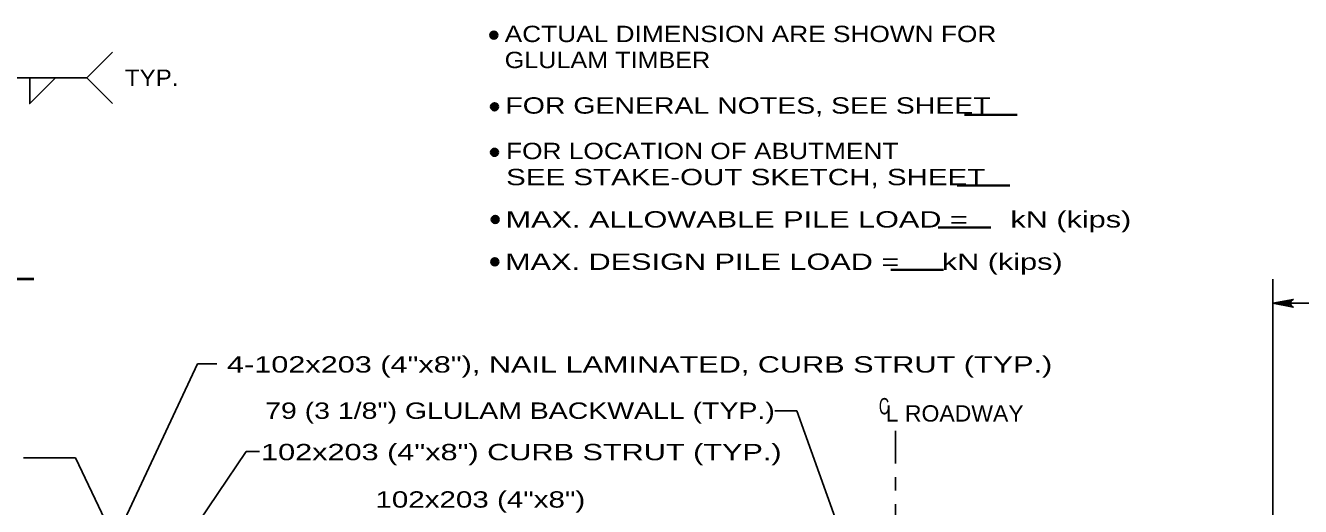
# Model space of a CAD drawing. Extents: x -6.4 to 73.1, y -66 to 0.
# Drawn here: x 41.66 to 51.01, y -58.56 to -55.03 of the extents above; entities that cross this region are included whole.
import ezdxf
from ezdxf.enums import TextEntityAlignment as Align

# ---------------------------------------------------------------- set-up
doc = ezdxf.new("R2010")
doc.units = 0
doc.header["$LTSCALE"] = 0.048
doc.linetypes.add('DOT_DASHED', pattern=[7.7, 5, -1.2, 0.3, -1.2])
for name, color, linetype, lineweight in [('3', 7, 'Continuous', 35), ('4', 7, 'Continuous', 25), ('5', 7, 'Continuous', 25)]:
    doc.layers.add(name, color=color, linetype=linetype, lineweight=lineweight)

msp = doc.modelspace()

# ---------------------------------------------------------------- hatches: boundary and pattern name
at = {"layer": '4'}
msp.add_hatch(color=256, dxfattribs=at).paths.add_polyline_path([(50.9215, -57.0485), (50.9215, -57.08783), (50.80342, -57.06817)])

# ---------------------------------------------------------------- linework, layer by layer
at = {"layer": '3', "lineweight": 25}
for p, q in [((42.10508, -55.41425), (42.29342, -55.22592)), ((40.91958, -55.41417), (42.10517, -55.41417)), ((42.10508, -55.41425), (42.29342, -55.60258))]:
    msp.add_line(p, q, dxfattribs=at)
msp.add_lwpolyline([(41.68692, -55.41417), (41.68692, -55.6025), (41.87525, -55.41417)], dxfattribs=at)
at = {"layer": '4', "lineweight": 35}
for p, q in [((48.54167, -55.68567), (48.92808, -55.68567)), ((48.48758, -56.20375), (48.874, -56.20375)), ((48.3485, -56.51308), (48.73492, -56.51308)), ((48.00067, -56.82242), (48.38708, -56.82242))]:
    msp.add_line(p, q, dxfattribs=at)
at = {"layer": '4', "lineweight": 40}
msp.add_line((38.4005, -56.88883), (41.71642, -56.88883), dxfattribs=at)
at = {"layer": '4'}
for p, q in [((50.80342, -58.64483), (50.80342, -56.891)), ((50.80342, -57.06817), (54.16433, -57.06817)), ((42.14542, -59.15942), (42.91742, -57.512)), ((42.91742, -57.512), (43.05942, -57.512)), ((47.31142, -57.85708), (47.15058, -57.85708)), ((47.67925, -58.88358), (47.31142, -57.85708)), ((42.41308, -59.43225), (43.27508, -58.15508)), ((43.27517, -58.15508), (43.37217, -58.15508)), ((42.26258, -58.70642), (42.02275, -58.203))]:
    msp.add_line(p, q, dxfattribs=at)
at = {"layer": '4', "linetype": 'DOT_DASHED'}
msp.add_line((48.03658, -58.003), (48.03658, -58.99125), dxfattribs=at)
at = {"layer": '4'}
msp.add_lwpolyline([(50.80342, -57.06817), (50.95258, -57.04017), (50.94108, -57.04817), (50.93517, -57.05817), (50.93342, -57.06817), (50.93517, -57.07817), (50.94108, -57.08817), (50.95258, -57.09617), (50.80342, -57.06817), (50.94108, -57.08817), (50.93517, -57.07817), (50.80342, -57.06817), (50.93342, -57.06817), (50.93517, -57.05817), (50.80342, -57.06817), (50.94108, -57.04817)], dxfattribs=at)
msp.add_lwpolyline([(50.9215, -57.0485), (50.9215, -57.08783), (50.80342, -57.06817)], close=True, dxfattribs=at)
at = {"layer": '4', "lineweight": 35}
for centre, radius in [((45.09097, -55.10047), 0.02667), ((45.09097, -55.10047), 0.02), ((45.09097, -55.10047), 0.01333), ((45.09097, -55.10047), 0.00667), ((45.09596, -55.62564), 0.02667), ((45.09596, -55.62564), 0.02), ((45.09596, -55.62564), 0.01333), ((45.09596, -55.62564), 0.00667), ((45.09596, -55.96056), 0.02667), ((45.09596, -55.96056), 0.02), ((45.09596, -55.96056), 0.01333), ((45.09596, -55.96056), 0.00667), ((45.10095, -56.45296), 0.02667), ((45.10095, -56.45296), 0.02), ((45.10095, -56.45296), 0.01333), ((45.10095, -56.45296), 0.00667), ((45.09757, -56.76368), 0.02667), ((45.09757, -56.76368), 0.02), ((45.09757, -56.76368), 0.01333), ((45.09757, -56.76368), 0.00667)]:
    msp.add_circle(centre, radius, dxfattribs=at)
at = {"layer": '5'}
msp.add_line((42.02283, -58.203), (41.64017, -58.203), dxfattribs=at)

# ---------------------------------------------------------------- texts
at = {"layer": '4'}
for s, width, p in [('ACTUAL DIMENSION ARE SHOWN FOR ', 1.2, (45.17017, -55.15142)), ('GLULAM TIMBER', 1.15, (45.17017, -55.34258)), ('FOR GENERAL NOTES, SEE SHEET    ', 1.3, (45.17517, -55.67658)), ('FOR LOCATION OF ABUTMENT', 1.2, (45.18017, -56.0105)), ('SEE STAKE-OUT SKETCH, SHEET    ', 1.35, (45.18017, -56.20175)), ('MAX. ALLOWABLE PILE LOAD =     kN (kips)', 1.4, (45.17683, -56.51242)), ('MAX. DESIGN PILE LOAD =     kN (kips)', 1.4, (45.17342, -56.82317))]:
    msp.add_text(s, height=0.12, dxfattribs=dict(at, width=width)).set_placement(p)
for s, width, p in [('TYP.', 1.1, (42.5815, -55.47283)), ('C', 0.65, (47.952, -57.88342)), ('L ROADWAY', 1.05, (48.47037, -57.93642))]:
    msp.add_text(s, height=0.12, dxfattribs=dict(at, width=width)).set_placement(p, align=Align.CENTER)
at = {"layer": '5'}
for s, width, p in [('4-102x203 (4"x8"), NAIL LAMINATED, CURB STRUT (TYP.)', 1.4, (43.13383, -57.57683)), ('79 (3 1/8") GLULAM BACKWALL (TYP.)', 1.3, (43.4135, -57.91625)), ('102x203 (4"x8") CURB STRUT (TYP.)', 1.4, (43.3835, -58.22017)), ('102x203 (4"x8")', 1.35, (44.22225, -58.56783))]:
    msp.add_text(s, height=0.12, dxfattribs=dict(at, width=width)).set_placement(p)

doc.saveas('drawing.dxf')
